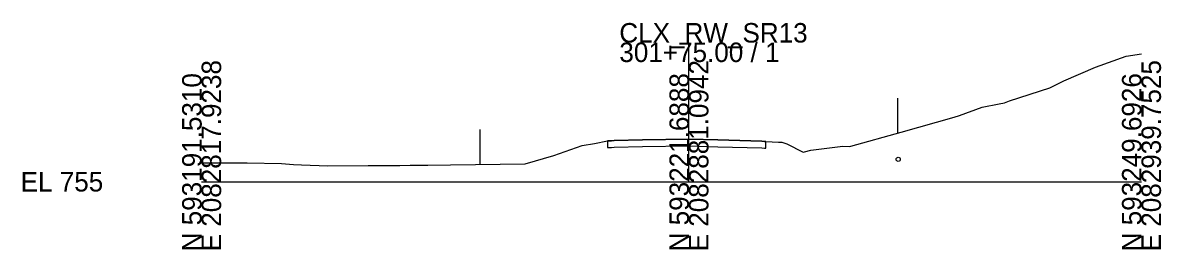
# Model space of a CAD drawing. Extents: x -26 to 2138, y -10 to 4518.
# Drawn here: x -25.7 to 137.8, y 990.3 to 1022.8 of the extents above; entities that cross this region are included whole.
import ezdxf

# ---------------------------------------------------------------- set-up
doc = ezdxf.new("R2010")
doc.units = 0
for name, color, linetype in [('GK_Cells', 7, 'Continuous'), ('MD_X_Asphalt_Pavement', 7, 'Continuous'), ('RW_X_Esmt_SH', 7, 'Continuous'), ('UT_X_Water', 7, 'Continuous'), ('XS_X_Ground_Line', 7, 'Continuous')]:
    doc.layers.add(name, color=color, linetype=linetype)

msp = doc.modelspace()

# ---------------------------------------------------------------- linework, layer by layer
at = {"layer": 'GK_Cells'}
for p, q in [((70, 1000), (70, 1020)), ((0, 1000), (70, 1000)), ((70, 1000), (135, 1000))]:
    msp.add_line(p, q, dxfattribs=at)
at = {"layer": 'MD_X_Asphalt_Pavement'}
msp.add_lwpolyline([(58.86, 1005.9), (58.3, 1005.86), (58.3, 1004.9), (58.86, 1004.94), (59.25, 1004.97), (63.31, 1005.05), (69.97, 1005.17), (74.13, 1005.04), (80.49, 1004.87), (80.84, 1004.84), (81.04, 1004.83), (81.04, 1005.79), (80.84, 1005.8), (80.49, 1005.83), (74.13, 1006), (69.97, 1006.13), (63.31, 1006.01), (59.25, 1005.93), (58.86, 1005.9)], dxfattribs=at)
at = {"layer": 'RW_X_Esmt_SH'}
for p, q in [((100, 1007.01), (100, 1012.01)), ((40, 1002.49), (40, 1007.49))]:
    msp.add_line(p, q, dxfattribs=at)
at = {"layer": 'UT_X_Water'}
msp.add_circle((100.06, 1003.22), 0.3, dxfattribs=at)
at = {"layer": 'XS_X_Ground_Line'}
msp.add_lwpolyline([(0, 1002.7), (2.16, 1002.71), (6.52, 1002.71), (11.45, 1002.62), (13.2, 1002.5), (14.35, 1002.44), (18.11, 1002.27), (23.94, 1002.32), (28.46, 1002.36), (29.95, 1002.37), (32.5, 1002.39), (35.73, 1002.42), (46.47, 1002.59), (50.6, 1003.77), (54.68, 1005.19), (56.42, 1005.51), (58.3, 1005.86), (58.86, 1005.9), (59.25, 1005.93), (63.31, 1006.01), (69.97, 1006.13), (74.13, 1006), (80.49, 1005.83), (80.84, 1005.8), (81.04, 1005.79), (82.87, 1005.68), (83.33, 1005.67), (84.08, 1005.46), (86.42, 1004.27), (86.59, 1004.31), (87.5, 1004.55), (92.09, 1005.12), (93.05, 1005.06), (93.27, 1005.12), (100.5, 1007.14), (108.08, 1009.27), (108.84, 1009.52), (112.13, 1010.71), (114.57, 1011.21), (115.35, 1011.35), (116.03, 1011.62), (121.83, 1013.48), (123.83, 1014.5), (128.38, 1016.48), (132.79, 1018.02), (135, 1018.36)], dxfattribs=at)

# ---------------------------------------------------------------- texts
msp.add_text('-', height=0.0001).set_placement((0, 1000))
at = {"layer": 'GK_Cells'}
for s, p in [('CLX_RW_SR13', (60, 1020)), ('301+75.00 / 1', (60, 1017.2)), ('EL 755', (-26, 998.6))]:
    msp.add_text(s, height=2.8, dxfattribs=at).set_placement(p)
for s, p in [('E 2082817.9238', (2.8, 990)), ('E 2082881.0942', (72.8, 990)), ('E 2082939.7525', (137.8, 990)), ('N 593191.5310', (0, 990)), ('N 593221.6888', (70, 990)), ('N 593249.6926', (135, 990))]:
    msp.add_text(s, height=2.8, rotation=90, dxfattribs=at).set_placement(p)

doc.saveas('drawing.dxf')
